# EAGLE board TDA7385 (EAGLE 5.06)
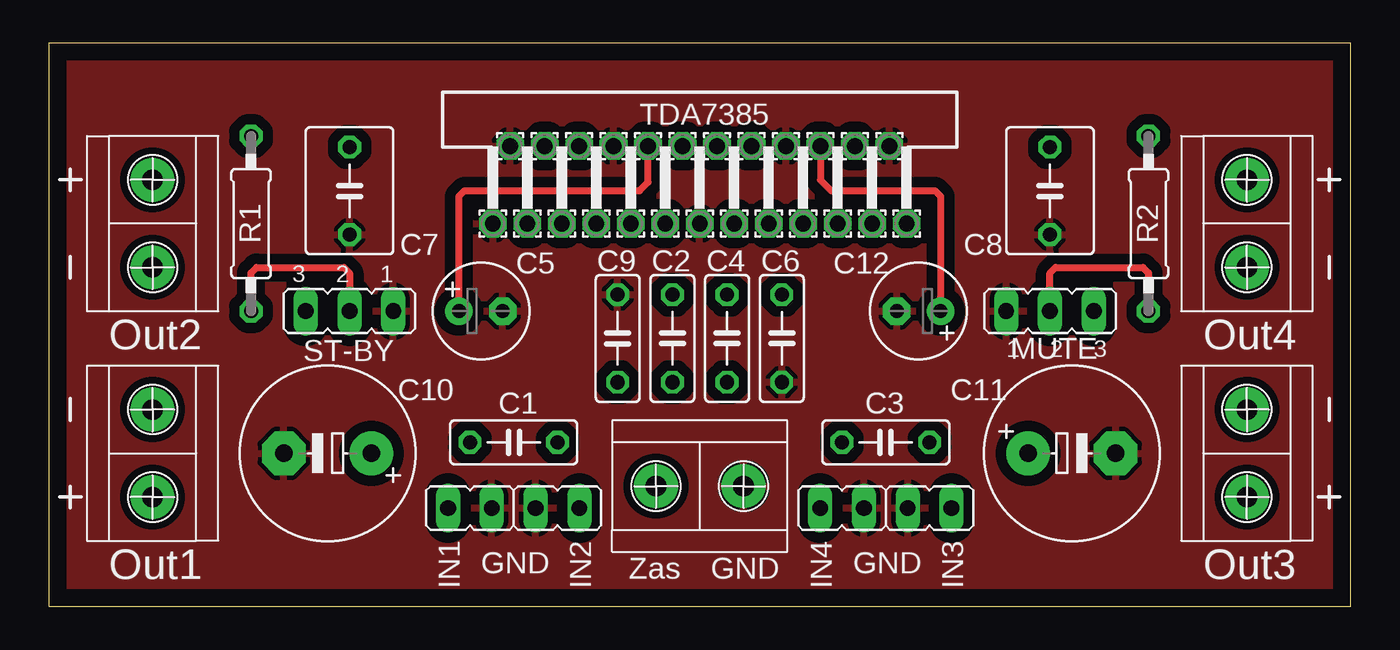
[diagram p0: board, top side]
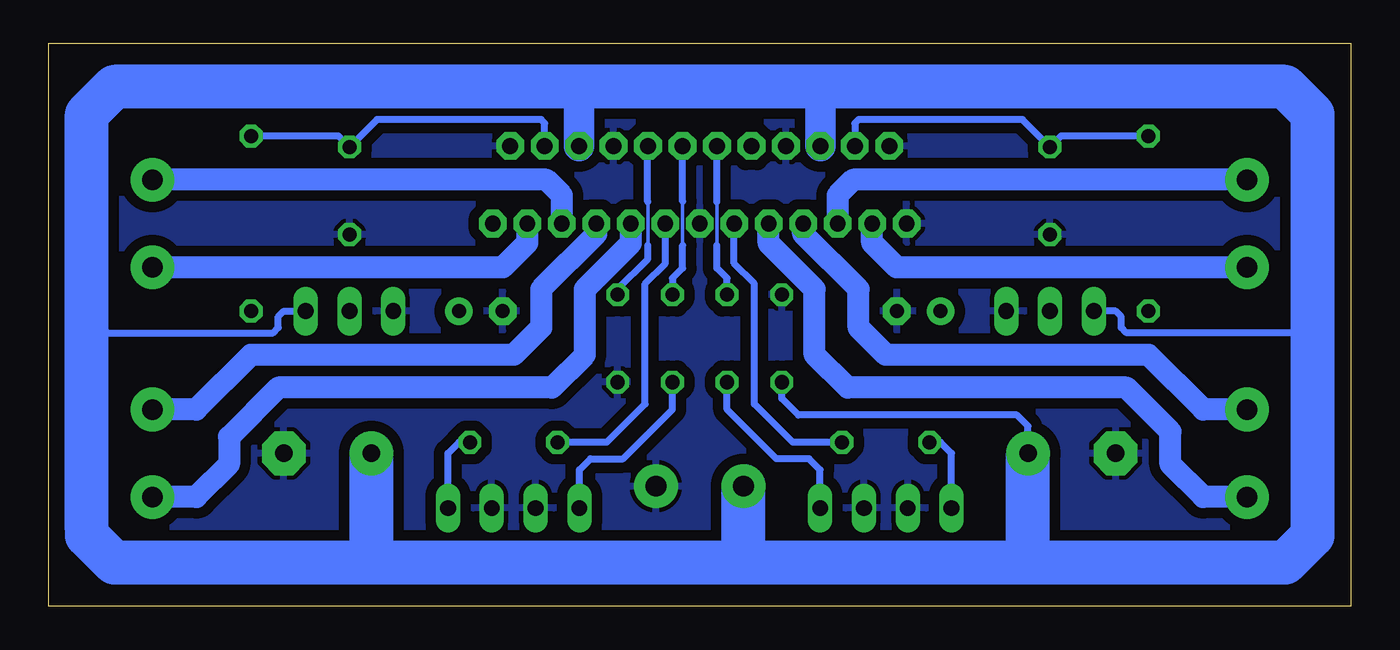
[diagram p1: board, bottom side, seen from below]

Size 75.55 x 32.69 mm. Coordinates in mm from the lower left corner, seen from the top.
Outline: 0,0 75.55,0 75.55,32.69 0,32.69 0,0
Copper layers (1*16): Top 0.035mm / dielectric 1.5mm / Bottom 0.035mm
Design rules "default": minimum track width 10mil, minimum drill 24mil, track to track 8mil, track to pad 8mil, pad to pad 8mil, via to via 8mil, smd to smd 8mil, copper to edge 40mil, drill to drill 8mil, minimum pad ring 10mil, minimum via ring 8mil, stop-mask expansion 4mil, vias tented up to drill 0mil, thermal gap 10mil

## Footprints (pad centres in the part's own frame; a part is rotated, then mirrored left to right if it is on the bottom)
C050-025X075 = drill 0.813 octagon: 1 -2.54,0; 2 2.54,0
E2,5-6 = drill 0.813 pad 1.6 round: + -1.27,0 | drill 0.813 pad 1.6 octagon: - 1.27,0
C050-050X075 = drill 0.813 octagon: 1 -2.54,0; 2 2.54,0
E5-10,5 = drill 1.016 pad 2.54 round: + -2.54,0 | drill 1.016 pad 2.54 octagon: - 2.54,0
JP1 = drill 0.914 long: 1 0,-1.27; 2 0,1.27
JP2 = drill 0.914 long: 1 -2.54,0; 2 0,0; 3 2.54,0
1,6/0,9 = drill 0.914 pad 1.6 octagon: 1 0,0
0207/10 = drill 0.813 octagon: 1 -5.08,0; 2 5.08,0
ARK2 = drill 1.2 pad 2.54 round: 1 -2.54,0; 3 2.54,0 | drill 0.8 pad 2.54 round: 2 2.54,0

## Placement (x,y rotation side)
C1  [C050-025X075]  26.99,9.53 0 top
C2  [C050-025X075]  36.2,15.56 90 top
C3  [C050-025X075]  48.58,9.53 180 top
C4  [C050-025X075]  39.37,15.56 90 top
C5  [E2,5-6]  25.08,17.14 0 top
C6  [C050-025X075]  42.55,15.56 90 top
C7  [C050-050X075]  17.46,24.13 270 top
C8  [C050-050X075]  58.1,24.13 270 top
C9  [C050-025X075]  33.02,15.56 270 top
C10  [E5-10,5]  16.19,8.89 180 top
C11  [E5-10,5]  59.37,8.89 0 top
C12  [E2,5-6]  50.48,17.14 180 top
IN1  [JP1]  24.45,5.71 270 top
IN2  [JP1]  29.53,5.71 90 top
IN3  [JP1]  51.12,5.71 270 top
IN4  [JP1]  46.04,5.71 90 top
MUTE  [JP2]  58.1,17.14 0 top
PAD1  [1,6/0,9]  25.78,22.23 0 top
PAD2  [1,6/0,9]  26.78,26.73 0 top
PAD3  [1,6/0,9]  27.78,22.23 0 top
PAD4  [1,6/0,9]  28.78,26.73 0 top
PAD5  [1,6/0,9]  29.78,22.23 0 top
PAD6  [1,6/0,9]  30.78,26.73 0 top
PAD7  [1,6/0,9]  31.78,22.23 0 top
PAD8  [1,6/0,9]  32.78,26.73 0 top
PAD9  [1,6/0,9]  33.78,22.23 0 top
PAD10  [1,6/0,9]  34.78,26.73 0 top
PAD11  [1,6/0,9]  35.78,22.23 0 top
PAD12  [1,6/0,9]  36.78,26.73 0 top
PAD13  [1,6/0,9]  37.78,22.23 0 top
PAD14  [1,6/0,9]  38.78,26.73 0 top
PAD15  [1,6/0,9]  39.78,22.23 0 top
PAD16  [1,6/0,9]  40.78,26.73 0 top
PAD17  [1,6/0,9]  41.78,22.23 0 top
PAD18  [1,6/0,9]  42.78,26.73 0 top
PAD19  [1,6/0,9]  43.78,22.23 0 top
PAD20  [1,6/0,9]  44.78,26.73 0 top
PAD21  [1,6/0,9]  45.78,22.23 0 top
PAD22  [1,6/0,9]  46.78,26.73 0 top
PAD23  [1,6/0,9]  47.78,22.23 0 top
PAD24  [1,6/0,9]  48.78,26.73 0 top
PAD25  [1,6/0,9]  49.78,22.23 0 top
R1  [0207/10]  11.75,22.23 90 top
R2  [0207/10]  63.82,22.23 90 top
ST-BY  [JP2]  17.46,17.14 180 top
U$1  ARK2  [ARK2]  6.03,8.89 270 top
U$2  ARK2  [ARK2]  6.03,22.23 90 top
U$3  ARK2  [ARK2]  69.53,8.89 270 top
U$4  ARK2  [ARK2]  69.53,22.23 90 top
U$9  ARK2  [ARK2]  37.78,6.99 180 top

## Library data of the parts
C1-C12 R1 R2 = rcl
IN1-IN4 MUTE ST-BY = jumper
PAD1-PAD25 = wirepad
U$1-U$4 U$9 = ark2

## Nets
GND: C5.- C6.1 C7.2 C8.2 C9.1 C10.- C11.- C12.- IN1.2 IN2.2 IN3.1 IN4.1 MUTE.1 PAD1.1 PAD2.1 PAD8.1 PAD13.1 PAD18.1 PAD24.1 ST-BY.1 U$9.1
N$1: PAD9.1 U$1.2
N$2: PAD7.1 U$1.1
N$3: PAD5.1 U$2.2
N$4: PAD3.1 U$2.1
N$5: PAD17.1 U$3.2
N$6: PAD19.1 U$3.1
N$7: PAD21.1 U$4.2
N$8: PAD23.1 U$4.1
N$9: C1.2 PAD11.1
N$10: C2.2 PAD12.1
N$11: R1.1 ST-BY.2
N$12: C3.2 PAD15.1
N$13: C4.2 PAD14.1
N$14: C5.+ PAD10.1
N$15: C6.2 PAD16.1
N$16: C7.1 PAD4.1 R1.2
N$17: C8.1 PAD22.1 R2.2
N$18: C9.2 C10.+ C11.+ C12.+ MUTE.3 PAD6.1 PAD20.1 ST-BY.3 U$9.2
N$19: C2.1 IN2.1
N$20: C3.1 IN3.2
N$21: C1.1 IN1.1
N$22: C4.1 IN4.2
N$23: MUTE.2 R2.1

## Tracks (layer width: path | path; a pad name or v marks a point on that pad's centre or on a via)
GND
  pour Bottom (isolate 0.61): -0.56,33.97 76.2,33.97 76.2,-0.32 -0.56,-0.32
  pour Top (isolate 0.61): -0.71,33.97 -0.71,-0.32 76.2,-0.32 76.2,33.97
N$1
  Bottom 1.27: U$1.2 8.57,6.35 10.48,8.25 10.48,10.16 13.02,12.7 29.21,12.7 31.11,14.61 31.11,18.42 33.78,21.08 PAD9.1
N$2
  Bottom 1.27: U$1.1 8.57,11.43 11.75,14.61 26.99,14.61 28.58,16.19 28.58,18.42 31.78,21.62 PAD7.1
N$3
  Bottom 1.27: U$2.2 28.89,24.77 29.78,23.88 PAD5.1
N$4
  Bottom 1.27: U$2.1 26.35,19.68 27.78,21.11 PAD3.1
N$5
  Bottom 1.27: U$3.2 66.99,6.35 65.09,8.25 65.09,9.84 62.23,12.7 46.36,12.7 44.45,14.61 44.45,18.42 41.78,21.08 PAD17.1
N$6
  Bottom 1.27: U$3.1 66.99,11.43 63.82,14.61 48.58,14.61 46.99,16.19 46.99,18.42 43.78,21.62 PAD19.1
N$7
  Bottom 1.27: U$4.2 46.67,24.77 45.78,23.88 PAD21.1
N$8
  Bottom 1.27: U$4.1 49.21,19.68 47.78,21.11 PAD23.1
N$9
  Bottom 0.406: C1.2 32.39,9.53 34.61,11.75 34.61,18.73 35.78,19.91 PAD11.1
N$10
  Bottom 0.203: 36.78,20.96 36.78,23.5
  Bottom 0.406: C2.2 36.19,19.05 36.78,19.64 36.78,20.96 | 36.78,23.5 PAD12.1 | 36.78,23.5
N$11
  Top 0.406: R1.1 11.75,19.37 12.06,19.68 17.15,19.68 17.46,19.37 ST-BY.2
N$12
  Bottom 0.406: C3.2 43.18,9.53 40.96,11.75 40.96,18.73 39.78,19.91 PAD15.1
N$13
  Bottom 0.203: 38.78,20.96 38.78,23.5
  Bottom 0.406: C4.2 39.37,19.05 38.78,19.64 38.78,20.96 | PAD14.1 38.78,23.51 38.78,23.5
N$14
  Top 0.406: C5.+ 23.81,23.81 24.13,24.13 34.29,24.13 34.78,24.62 PAD10.1
N$15
  Bottom 0.203: 40.79,20.96 40.79,23.5
  Bottom 0.406: C6.2 42.54,18.42 40.79,20.17 40.79,20.96 | PAD16.1 40.8,26.08 40.8,23.5 40.79,23.5
N$16
  Bottom 0.406: R1.2 16.83,27.31 C7.1 19.05,28.26 28.58,28.26 28.78,28.05 PAD4.1
N$17
  Bottom 0.406: R2.2 58.74,27.31 C8.1 56.51,28.26 46.99,28.26 46.78,28.05 PAD22.1
N$18
  Top 0.406: C12.+ 51.75,23.81 51.43,24.13 45.4,24.13 44.78,24.75 PAD20.1
  Bottom 0.406: C10.+ 18.73,10.48 19.37,11.11 32.07,11.11 33.02,12.07 C9.2 | 56.83,2.54 71.44,2.54 73.34,4.45 | 46.67,29.85 46.99,30.16 71.44,30.16 73.34,28.26 73.34,15.88 62.55,15.88 62.23,16.19 62.23,16.83 61.91,17.14 MUTE.3 | ST-BY.3 13.65,17.14 13.33,16.83 13.33,16.19 13.02,15.88 2.22,15.88
  Bottom 1.778: PAD6.1 30.78,30.15 30.8,30.16 | PAD20.1 44.78,30.15 44.77,30.16
  Bottom 2.54: 56.83,2.54 C11.+ | 18.73,2.54 35.24,2.54 | 35.24,2.54 56.83,2.54 | 18.73,2.54 C10.+ | 35.24,2.54 U$9.2 | 18.73,2.54 3.81,2.54 2.22,4.13 2.22,15.88 2.22,28.57 3.81,30.16 30.8,30.16 44.77,30.16 71.44,30.16 71.75,30.16 73.34,28.57 73.34,15.88 73.34,4.45 73.34,4.13 71.75,2.54 56.83,2.54
N$19
  Bottom 0.406: IN2.1 30.8,7.94 31.43,8.57 33.34,8.57 36.19,11.43 C2.1
N$20
  Bottom 0.406: IN3.2 52.39,8.89 51.75,9.53 C3.1
N$21
  Bottom 0.406: IN1.1 23.18,8.89 23.81,9.53 C1.1
N$22
  Bottom 0.406: IN4.2 44.77,7.94 44.13,8.57 42.23,8.57 39.37,11.43 C4.1
N$23
  Top 0.406: R2.1 63.82,19.37 63.5,19.68 58.42,19.68 58.1,19.37 MUTE.2

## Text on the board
tPlace: TDA7385 | Out2 | Out4 | Out1 | GND | Zas | GND | GND | Out3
